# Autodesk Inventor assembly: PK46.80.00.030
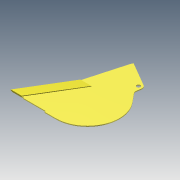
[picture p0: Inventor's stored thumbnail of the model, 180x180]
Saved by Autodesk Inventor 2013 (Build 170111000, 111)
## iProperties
Shininess: 64.0
Length Units: 11269
Angle Units: 11279
Time Units: 11290
Mass Units: 11283
Length Display Precision: 3
Angle Display Precision: 2
Compacted: True
Created: 2005-01
Part Number: PK46.80.00.030
Document SubType Name: Assembly
Designer: SAlex
Manufacturer: Standard
Standards Organization: Custom
Density: 0.0
Volumn: 0.0
Area: 0.0
PropertySet Name: Model Information
Control State: 0
Master: False
Checked Out: False
Checked Out Date: 2008-10-15
Last Check In Date: 2008-10-15
Author: SAlex
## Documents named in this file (3)
- D:\FrontLoaderVault\Data\Assy, Chassis, Front\PK46.80.00.030.iam
- D:\FrontLoaderVault\Data\Assy, Chassis, Front\PK46.80.00.017.ipt
- D:\FrontLoaderVault\Data\Assy, Chassis, Front\PK46.80.00.019.ipt
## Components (2 placed, 2 different names)
1. PK46.80.00.017:1 — Mate:1, Flush:1, Mate:2
2. PK46.80.00.019:1 — Mate:1, Flush:1, Mate:2
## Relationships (3: Mate 2, Flush 1)
- Mate:1: PK46.80.00.017:1 ↔ PK46.80.00.019:1
- Flush:1: PK46.80.00.017:1 ↔ PK46.80.00.019:1
- Mate:2: PK46.80.00.017:1 ↔ PK46.80.00.019:1
